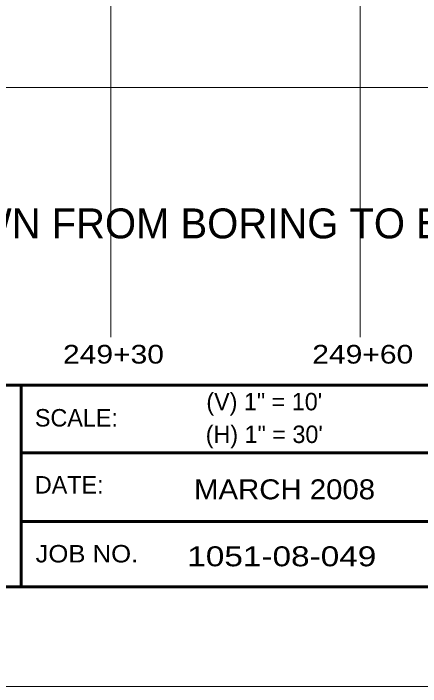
# Model space of a CAD drawing. Extents: x -76 to 974, y -1080 to -735.
# Drawn here: x 179.48 to 195.81, y -1056.11 to -1029.12 of the extents above; entities that cross this region are included whole.
import ezdxf
from ezdxf.enums import TextEntityAlignment as Align

# ---------------------------------------------------------------- set-up
doc = ezdxf.new("R2010")
doc.units = 0
doc.header["$LTSCALE"] = 0.36
doc.layers.add('21', color=7, linetype='Continuous')
doc.layers.add('29', color=7, linetype='Continuous')
doc.layers.add('63', color=7, linetype='Continuous', lineweight=35)
doc.layers.add('7', color=7, linetype='Continuous', lineweight=13)

msp = doc.modelspace()

# ---------------------------------------------------------------- linework, layer by layer
at = {"layer": '63', "lineweight": 60}
for p, q in [((179.7827, -1052.1123), (179.7827, -1044.0258)), ((179.7827, -1046.7337), (212.515, -1046.7337)), ((179.7827, -1049.4971), (212.515, -1049.4971))]:
    msp.add_line(p, q, dxfattribs=at)
at = {"layer": '63'}
msp.add_line((112.515, -1052.1123), (212.515, -1052.1123), dxfattribs=at)
at = {"layer": '63', "lineweight": 13}
msp.add_line((217.515, -1056.1123), (107.515, -1056.1123), dxfattribs=at)
at = {"layer": '63', "lineweight": 60}
msp.add_lwpolyline([(112.515, -1044.0258), (212.515, -1044.0258), (212.515, -1052.1123), (112.515, -1052.1123)], close=True, dxfattribs=at)
at = {"layer": '7'}
for p, q in [((183.3912, -1042.0988), (183.3912, -895.7205)), ((193.3912, -1042.0988), (193.3912, -895.7205)), ((122.0054, -1032.09), (208.0761, -1032.09))]:
    msp.add_line(p, q, dxfattribs=at)

# ---------------------------------------------------------------- texts
at = {"layer": '21'}
for s, p in [('(V) 1" = 10\'', (189.5407, -1045.0345)), ('(H) 1" = 30\'', (189.5405, -1046.3452))]:
    msp.add_text(s, height=0.7, dxfattribs=at).set_placement(p, align=Align.CENTER)
at = {"layer": '29'}
msp.add_text('NOTE: STRATIGRAPHY IS DRAWN FROM BORING TO BORING.', height=1.2, dxfattribs=at).set_placement((178.3362, -1038.137), align=Align.CENTER)
at = {"layer": '63'}
for s, height, width, p in [('249+30', 0.75, 1.2, (183.4917, -1043.1595)), ('249+60', 0.75, 1.2, (193.4917, -1043.1595)), ('MARCH 2008', 0.8, 1.1, (190.3543, -1048.6023)), ('1051-08-049', 0.8, 1.25, (190.2441, -1051.2891))]:
    msp.add_text(s, height=height, dxfattribs=dict(at, width=width)).set_placement(p, align=Align.CENTER)
for s, p in [('SCALE:', (180.3398, -1045.683)), ('DATE:', (180.3398, -1048.372))]:
    msp.add_text(s, height=0.6999, dxfattribs=at).set_placement(p)
at = {"layer": '63', "width": 1.1}
msp.add_text('JOB NO.', height=0.6999, dxfattribs=at).set_placement((180.3668, -1051.135))

doc.saveas('drawing.dxf')
